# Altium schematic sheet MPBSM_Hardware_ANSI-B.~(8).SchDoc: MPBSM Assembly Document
size 431 x 279 mm; Date: Not shown in title block; ApprovedBy: Not shown in title block; CheckedBy: Not shown in title block; Author: Not shown in title block; CompanyName: Not shown in title block; Engineer: Not shown in title block; Organization: Not shown in title block; Address1: Not shown in title block; Address2: Not shown in title block; Address3: Not shown in title block; Address4: Not shown in title block; DocumentNumber: 12; Revision: Use project parameter SCH_Rev; SheetNumber: 12; SheetTotal: 12; PageSetup: Record=PageOptions¦CenterHorizontal=True¦CenterVertical=True¦PrintScale=1.00¦XCorrection=1.00¦YCorrection=1.00¦PrintKind=0¦BorderSize=5000000¦LeftOffset=0¦BottomOffset=0¦Orientation=2¦PaperLength=1000¦PaperWidth=1000¦Scale=100¦PaperSource=15¦PrintQuality=600¦MediaType=1¦DitherType=10¦PaperKind=Letter¦PrintScaleMode=1
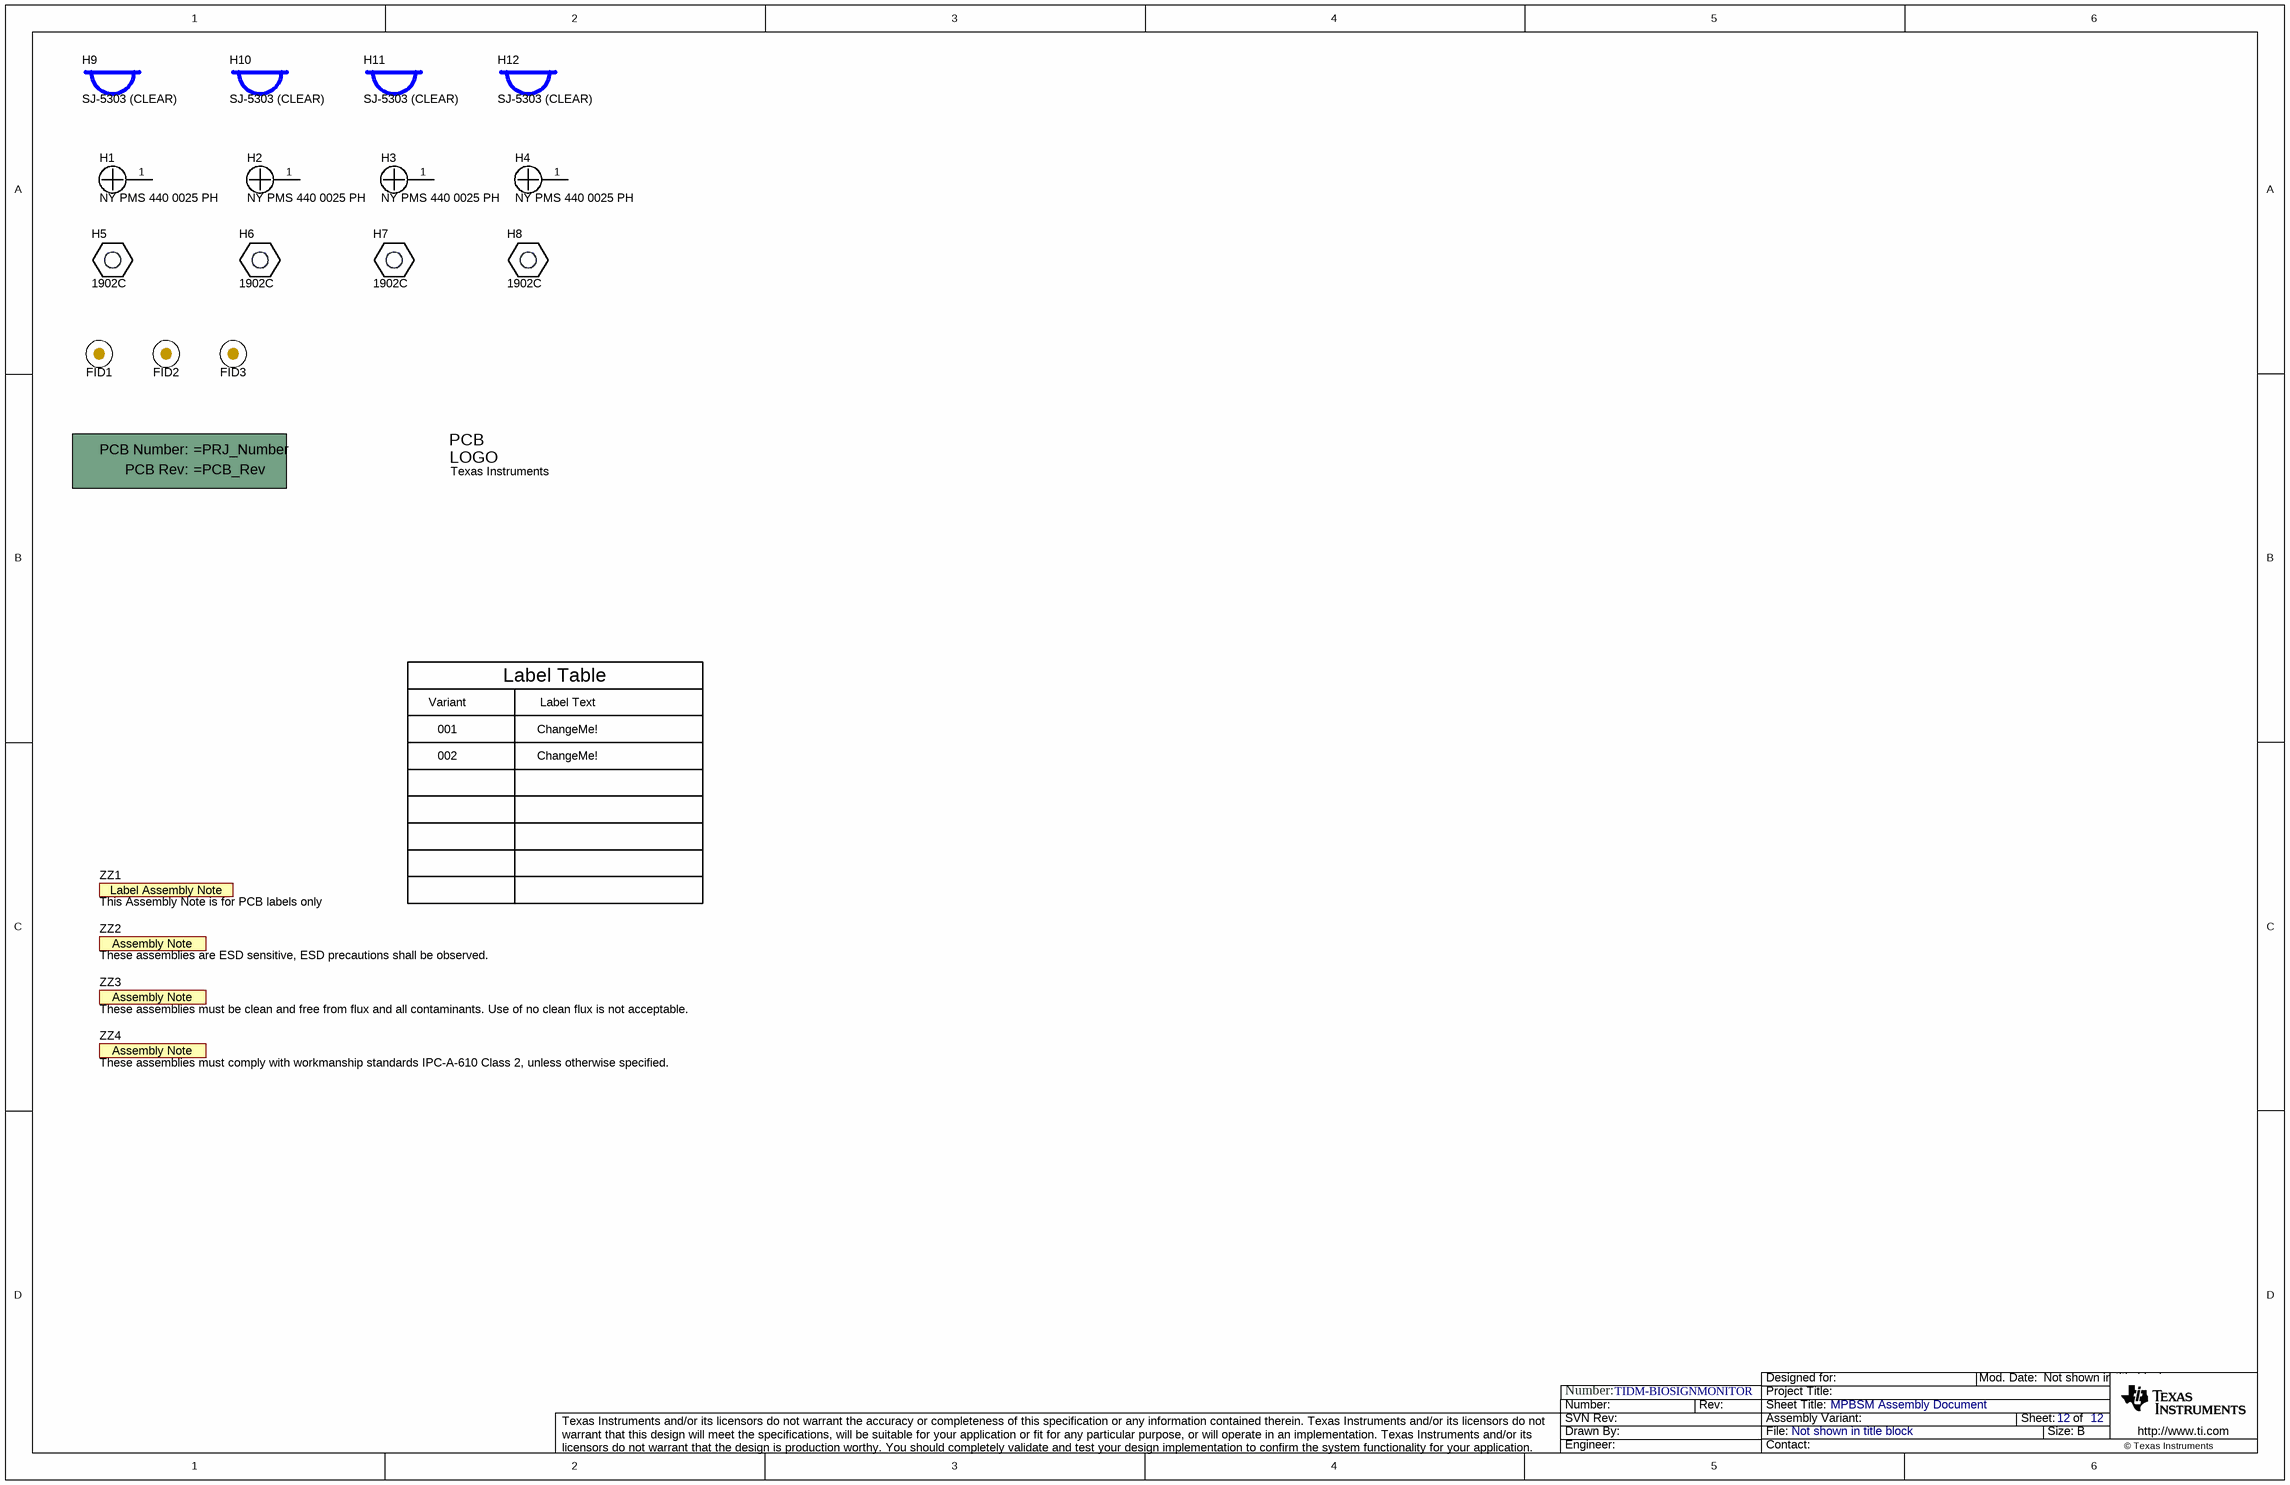
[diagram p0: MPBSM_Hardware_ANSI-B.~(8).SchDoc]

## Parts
!PCB1  Printed Circuit Board  (value not drawn)  (mechanical)
FID1  Fiducial  [Fiducial10-20]  (value not drawn)
FID2  Fiducial  [Fiducial10-20]  (value not drawn)
FID3  Fiducial  [Fiducial10-20]  (value not drawn)
H1  NY PMS 440 0025 PH  [NY PMS 440 0025 PH]
H2  NY PMS 440 0025 PH  [NY PMS 440 0025 PH]
H3  NY PMS 440 0025 PH  [NY PMS 440 0025 PH]
H4  NY PMS 440 0025 PH  [NY PMS 440 0025 PH]
H5  1902C  [Keystone_1902C]
H6  1902C  [Keystone_1902C]
H7  1902C  [Keystone_1902C]
H8  1902C  [Keystone_1902C]
H9  SJ-5303 (CLEAR)  [Bumpon_SJ5003Transparent]
H10  SJ-5303 (CLEAR)  [Bumpon_SJ5003Transparent]
H11  SJ-5303 (CLEAR)  [Bumpon_SJ5003Transparent]
H12  SJ-5303 (CLEAR)  [Bumpon_SJ5003Transparent]
Logo1  Texas Instruments  [TI_Symbol_Overlay_Small]  (no BOM)
ZZ1  This Assembly Note is for PCB labels only  [AssemblyNoteLabel]  (no BOM)
ZZ2  These assemblies are ESD sensitive, ESD precautions shall be observed.  [AssemblyNote]  (no BOM)
ZZ3  These assemblies must be clean and free from flux and all contaminants. Use of no clean flux is not acceptable.  [AssemblyNote]  (no BOM)
ZZ4  These assemblies must comply with workmanship standards IPC-A-610 Class 2, unless otherwise specified.  [AssemblyNote]  (no BOM)

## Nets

Not connected (* = marked no-connect by the designer): H1 1; H2 1; H3 1; H4 1

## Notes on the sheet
- Variant
- Label Table
- Label Text
- 001
- 002
- ChangeMe!
- Number:
- TIDM-BIOSIGNMONITOR

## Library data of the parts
!PCB1 = PCB: Manufacturer: Any; SymbolCreator: a0412235
FID1-FID3 = Fiducial: Fiducial mark.  There is nothing to buy or mount.; SymbolCreator: codlsc
H1-H4 = NY PMS 440 0025 PH: Machine Screw, Round, #4-40 x 1/4, Nylon, Philips panhead; Manufacturer: B&F Fastener Supply; CompType: Hardware; SymbolCreator: codlsc; U/M: EA
H5-H8 = 1902C: Standoff, Hex, 0.5"L #4-40 Nylon; Manufacturer: Keystone; CompType: Hardware
H9-H12 = SJ-5303 (CLEAR): Bumpon, Hemisphere, 0.44 X 0.20, Clear; Manufacturer: 3M; SymbolCreator: a0412235
Logo1 = TI_Logo: Texas Instrument Corporate Signature; SymbolCreator: codlsc
ZZ1 = AssemblyNoteLabel: SymbolCreator: a0412235
ZZ2-ZZ4 = AssemblyNote: SymbolCreator: codlsc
